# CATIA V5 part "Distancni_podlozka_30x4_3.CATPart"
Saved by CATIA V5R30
Part number: dosedaci_podlozka_30x4_3
Definition: E 1500_30x4
Nomenclature: E 1500_30x4
Source: Unknown
Description: PART--DESC
Bounding box of the stored display mesh (mm): x -219 to -189, y -105 to -75, z -224 to -220
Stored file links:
  E:\Bakalarka\Model\Forma_v7\Distancni_podlozka_30x4_3.CATPart
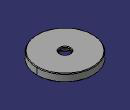
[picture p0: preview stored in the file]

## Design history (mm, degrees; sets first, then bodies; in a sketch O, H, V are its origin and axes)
Body1 "MANIFOLD_SOLID_BREP #4082" (main body)
  Solid1: solid without history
